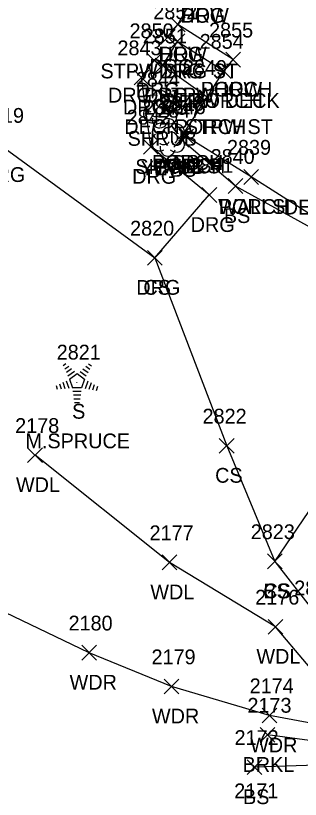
# Model space of a CAD drawing. Extents: x 1499292 to 1501024, y 534584 to 538043.
# Drawn here: x 1499668.2 to 1499706.6, y 537627.9 to 537733.8 of the extents above; entities that cross this region are included whole.
import ezdxf

# ---------------------------------------------------------------- set-up
doc = ezdxf.new("R2010")
doc.units = 0
for name, color, linetype in [('L_A', 7, 'Continuous'), ('L_C', 7, 'Continuous'), ('L_I', 7, 'Continuous'), ('L_TIC', 7, 'Continuous'), ('LAWA', 7, 'Continuous'), ('LAWE', 7, 'Continuous'), ('LBC', 7, 'Continuous'), ('LBF', 7, 'Continuous'), ('LELB', 7, 'Continuous'), ('LSH', 7, 'Continuous'), ('LTC', 7, 'Continuous'), ('LWS', 7, 'Continuous'), ('R_A', 7, 'Continuous'), ('R_I', 7, 'Continuous'), ('R_TIC', 7, 'Continuous'), ('RDG', 7, 'Continuous')]:
    doc.layers.add(name, color=color, linetype=linetype)

msp = doc.modelspace()

# ---------------------------------------------------------------- linework, layer by layer
at = {"layer": 'L_TIC'}
for points in [[(1499689.11, 537731.64), (1499691.11, 537733.64)], [(1499691.11, 537731.64), (1499689.11, 537733.64)], [(1499689.06, 537729.36), (1499691.06, 537731.36)], [(1499691.06, 537729.36), (1499689.06, 537731.36)], [(1499696.59, 537726.89), (1499698.59, 537728.89)], [(1499698.59, 537726.89), (1499696.59, 537728.89)], [(1499696.59, 537726.89), (1499698.59, 537728.89)], [(1499698.59, 537726.89), (1499696.59, 537728.89)], [(1499687.07, 537726.09), (1499689.07, 537728.09)], [(1499689.07, 537726.09), (1499687.07, 537728.09)], [(1499695.32, 537725.36), (1499697.32, 537727.36)], [(1499697.32, 537725.36), (1499695.32, 537727.36)], [(1499695.32, 537725.36), (1499697.32, 537727.36)], [(1499697.32, 537725.36), (1499695.32, 537727.36)], [(1499693.06, 537721.83), (1499695.06, 537723.83)], [(1499695.06, 537721.83), (1499693.06, 537723.83)], [(1499693.06, 537721.83), (1499695.06, 537723.83)], [(1499695.06, 537721.83), (1499693.06, 537723.83)], [(1499689.99, 537716.99), (1499691.99, 537718.99)], [(1499691.99, 537716.99), (1499689.99, 537718.99)], [(1499689.99, 537716.99), (1499691.99, 537718.99)], [(1499691.99, 537716.99), (1499689.99, 537718.99)], [(1499689.59, 537716.05), (1499691.59, 537718.05)], [(1499691.59, 537716.05), (1499689.59, 537718.05)], [(1499690.25, 537716.51), (1499692.25, 537718.51)], [(1499692.25, 537716.51), (1499690.25, 537718.51)], [(1499690.25, 537716.51), (1499692.25, 537718.51)], [(1499692.25, 537716.51), (1499690.25, 537718.51)], [(1499699.02, 537711.03), (1499701.02, 537713.03)], [(1499701.02, 537711.03), (1499699.02, 537713.03)], [(1499699.02, 537711.03), (1499701.02, 537713.03)], [(1499701.02, 537711.03), (1499699.02, 537713.03)], [(1499696.89, 537709.8), (1499698.89, 537711.8)], [(1499698.89, 537709.8), (1499696.89, 537711.8)], [(1499686.02, 537700.1), (1499688.02, 537702.1)], [(1499688.02, 537700.1), (1499686.02, 537702.1)], [(1499695.71, 537674.68), (1499697.71, 537676.68)], [(1499697.71, 537674.68), (1499695.71, 537676.68)], [(1499669.84, 537673.41), (1499671.84, 537675.41)], [(1499671.84, 537673.41), (1499669.84, 537675.41)], [(1499687.98, 537658.91), (1499689.98, 537660.91)], [(1499689.98, 537658.91), (1499687.98, 537660.91)], [(1499702.22, 537659.05), (1499704.22, 537661.05)], [(1499704.22, 537659.05), (1499702.22, 537661.05)], [(1499702.22, 537659.05), (1499704.22, 537661.05)], [(1499704.22, 537659.05), (1499702.22, 537661.05)], [(1499702.31, 537650.2), (1499704.31, 537652.2)], [(1499704.31, 537650.2), (1499702.31, 537652.2)], [(1499677.14, 537646.7), (1499679.14, 537648.7)], [(1499679.14, 537646.7), (1499677.14, 537648.7)], [(1499688.26, 537642.13), (1499690.26, 537644.13)], [(1499690.26, 537642.13), (1499688.26, 537644.13)], [(1499701.5, 537638.21), (1499703.5, 537640.21)], [(1499703.5, 537638.21), (1499701.5, 537640.21)], [(1499701.21, 537635.58), (1499703.21, 537637.58)], [(1499703.21, 537635.58), (1499701.21, 537637.58)], [(1499699.46, 537631.22), (1499701.46, 537633.22)], [(1499701.46, 537631.22), (1499699.46, 537633.22)]]:
    msp.add_lwpolyline(points, dxfattribs=at)
at = {"layer": 'LAWA'}
for points in [[(1499794.25, 537673.22), (1499784.11, 537668.52), (1499774.16, 537666.01), (1499760.16, 537658.55), (1499756.14, 537654.93), (1499740.5, 537649.76), (1499726.86, 537641.25), (1499716.88, 537640.03), (1499711.65, 537641.29), (1499703.31, 537651.2), (1499688.98, 537659.91), (1499670.84, 537674.41)], [(1499794.25, 537673.22), (1499786.26, 537665.9), (1499777.3, 537661.84), (1499770.76, 537658.32), (1499756.42, 537650.43), (1499743.07, 537644.05), (1499716.52, 537636.59), (1499702.5, 537639.21), (1499689.26, 537643.13), (1499678.14, 537647.7), (1499664.49, 537654.21)]]:
    msp.add_lwpolyline(points, dxfattribs=at)
at = {"layer": 'LAWE'}
msp.add_lwpolyline([(1499799.84, 537680.23), (1499787.98, 537665.18), (1499777.71, 537659.05), (1499769.67, 537656.09), (1499756.09, 537648.19), (1499744.55, 537642.26), (1499733.94, 537634.94), (1499716.58, 537634.66), (1499702.21, 537636.58)], dxfattribs=at)
at = {"layer": 'LBC'}
msp.add_lwpolyline([(1499697.59, 537727.89), (1499690.11, 537732.64), (1499693.07, 537737.88), (1499694.33, 537739.7), (1499698.3, 537745.63), (1499698.59, 537746.05), (1499699.21, 537747.22), (1499705.4, 537743.45), (1499710.54, 537740.08), (1499716.25, 537736.71), (1499721.75, 537745), (1499738.99, 537733.64), (1499732.1, 537722.82), (1499729.12, 537718.08), (1499724.69, 537711.28), (1499721.27, 537713.24)], dxfattribs=at)
at = {"layer": 'LBF'}
for points in [[(1499694.06, 537722.83), (1499688.07, 537727.09), (1499690.06, 537730.36), (1499696.32, 537726.36)], [(1499711.51, 537704.76), (1499700.02, 537712.03), (1499691.25, 537717.51), (1499690.99, 537717.99), (1499694.06, 537722.83), (1499696.32, 537726.36), (1499697.59, 537727.89)]]:
    msp.add_lwpolyline(points, dxfattribs=at)
at = {"layer": 'LELB'}
for points in [[(1499931.33, 537841.3), (1499922.8, 537827.37), (1499912.72, 537807.85), (1499905.96, 537796.12), (1499895.82, 537778.01), (1499880.55, 537762.56), (1499870.86, 537749.78), (1499857.65, 537732.09), (1499849.89, 537720.06), (1499839.9, 537710.15), (1499830.87, 537699.25), (1499819.75, 537691.27), (1499813.25, 537682.44), (1499807.24, 537678.73), (1499801.4, 537680.95), (1499789.92, 537664.22), (1499779.13, 537655.09), (1499771.86, 537652.25), (1499758.58, 537645.46), (1499745.45, 537639.29), (1499734.4, 537633.25), (1499715.96, 537632.7), (1499700.46, 537632.22)], [(1499703.22, 537660.05), (1499717.83, 537681.58), (1499716.65, 537701.98), (1499709.84, 537704.22), (1499697.89, 537710.8), (1499690.59, 537717.05), (1499690.99, 537717.99)], [(1499687.02, 537701.1), (1499696.71, 537675.68), (1499703.22, 537660.05), (1499709.09, 537652.45)]]:
    msp.add_lwpolyline(points, dxfattribs=at)
at = {"layer": 'LSH'}
for p, q in [((1499687.7, 537721.24), (1499687.7, 537721.24)), ((1499687.7, 537721.24), (1499687.7, 537721.24)), ((1499688.75, 537717.44), (1499688.75, 537717.44)), ((1499688.75, 537717.44), (1499688.75, 537717.44))]:
    msp.add_line(p, q, dxfattribs=at)
for centre in [(1499687.75, 537722.68), (1499688.79, 537718.87)]:
    msp.add_arc(centre, 1.05, 335.5272, 180.9563, dxfattribs=at)
for centre, major_axis, ratio, start_param, end_param in [((1499686.91, 537721.91), (1.21, -0.51), 0.895232, 1.570796, 4.712389), ((1499688.74, 537721.83), (-1.14, -0.48), 0.949671, 1.570796, 4.712389), ((1499687.49, 537721.7), (-0.208, -0.792), 0.645439, 3.141593, 6.283185), ((1499688.2, 537721.08), (-0.5, 0.667), 0.989748, 3.141593, 6.283185), ((1499686.62, 537720.54), (0.58, -1.04), 0.959034, 3.141593, 6.283185), ((1499688.7, 537720.41), (-1.09, 0.79), 0.841452, 1.570796, 4.712389), ((1499687.7, 537719.74), (0.26, 1.06), 0.942809, 1.570796, 4.712389), ((1499687.24, 537720.49), (-0.625, -0.083), 0.423636, 0, 3.141593), ((1499687.96, 537718.1), (1.21, -0.51), 0.895232, 1.570796, 4.712389), ((1499689.79, 537718.02), (-1.14, -0.48), 0.949671, 1.570796, 4.712389), ((1499688.54, 537717.9), (-0.208, -0.792), 0.645439, 3.141593, 6.283185), ((1499689.25, 537717.27), (-0.5, 0.667), 0.989748, 3.141593, 6.283185), ((1499687.66, 537716.73), (0.58, -1.04), 0.959034, 3.141593, 6.283185), ((1499688.29, 537716.69), (-0.625, -0.083), 0.423636, 0, 3.141593), ((1499689.75, 537716.6), (-1.09, 0.79), 0.841452, 1.570796, 4.712389), ((1499688.75, 537715.94), (0.26, 1.06), 0.942809, 1.570796, 4.712389)]:
    msp.add_ellipse(centre, major_axis=major_axis, ratio=ratio, start_param=start_param, end_param=end_param, dxfattribs=at)
at = {"layer": 'LTC'}
for p, q in [((1499674.65, 537686.54), (1499675.01, 537686.8)), ((1499674.86, 537686.08), (1499675.39, 537686.46)), ((1499675.07, 537685.61), (1499675.78, 537686.12)), ((1499677.31, 537686.09), (1499677.99, 537685.59)), ((1499677.68, 537686.44), (1499678.23, 537686.04)), ((1499678.05, 537686.78), (1499678.47, 537686.48)), ((1499675.28, 537685.15), (1499676.16, 537685.78)), ((1499675.51, 537684.69), (1499676.52, 537685.43)), ((1499676.52, 537685.43), (1499677.51, 537684.7)), ((1499676.94, 537685.74), (1499677.75, 537685.15)), ((1499674.14, 537684.04), (1499674.35, 537683.39)), ((1499674.6, 537684.26), (1499674.87, 537683.42)), ((1499675.05, 537684.47), (1499675.38, 537683.45)), ((1499675.51, 537684.69), (1499675.89, 537683.5)), ((1499677.51, 537684.7), (1499677.12, 537683.5)), ((1499677.95, 537684.43), (1499677.61, 537683.39)), ((1499678.4, 537684.18), (1499678.11, 537683.3)), ((1499678.84, 537683.93), (1499678.6, 537683.2)), ((1499673.68, 537683.82), (1499673.84, 537683.35)), ((1499677.12, 537683.5), (1499675.89, 537683.5)), ((1499677.08, 537683), (1499675.94, 537683)), ((1499679.29, 537683.68), (1499679.1, 537683.11)), ((1499677, 537682.5), (1499676.01, 537682.5)), ((1499676.92, 537682), (1499676.09, 537682)), ((1499676.83, 537681.5), (1499676.16, 537681.5))]:
    msp.add_line(p, q, dxfattribs=at)
at = {"layer": 'LWS'}
msp.add_lwpolyline([(1499730.18, 537700.09), (1499717.54, 537704.27), (1499711.51, 537704.76), (1499700.02, 537712.03), (1499691.25, 537717.51)], dxfattribs=at)
at = {"layer": 'R_TIC'}
for points in [[(1499689.11, 537731.64), (1499691.11, 537733.64)], [(1499691.11, 537731.64), (1499689.11, 537733.64)], [(1499687.77, 537729.96), (1499689.77, 537731.96)], [(1499689.77, 537729.96), (1499687.77, 537731.96)], [(1499689.06, 537729.36), (1499691.06, 537731.36)], [(1499691.06, 537729.36), (1499689.06, 537731.36)], [(1499685.94, 537726.79), (1499687.94, 537728.79)], [(1499687.94, 537726.79), (1499685.94, 537728.79)], [(1499687.07, 537726.09), (1499689.07, 537728.09)], [(1499689.07, 537726.09), (1499687.07, 537728.09)], [(1499684.22, 537724.48), (1499686.22, 537726.48)], [(1499686.22, 537724.48), (1499684.22, 537726.48)], [(1499685.47, 537715.11), (1499687.47, 537717.11)], [(1499687.47, 537715.11), (1499685.47, 537717.11)], [(1499693.36, 537708.59), (1499695.36, 537710.59)], [(1499695.36, 537708.59), (1499693.36, 537710.59)], [(1499686.02, 537700.1), (1499688.02, 537702.1)], [(1499688.02, 537700.1), (1499686.02, 537702.1)]]:
    msp.add_lwpolyline(points, dxfattribs=at)
at = {"layer": 'RDG'}
for points in [[(1499616.25, 537822.18), (1499611.44, 537814.18), (1499628, 537804.72), (1499648.23, 537793.6), (1499657.65, 537787.04), (1499661.23, 537780.56), (1499662.78, 537771.71), (1499664.29, 537756.49), (1499660.39, 537740.63), (1499648.73, 537728.57), (1499635.52, 537714.66), (1499643.06, 537703.46), (1499654.08, 537709.78), (1499666.1, 537716.35), (1499687.02, 537701.1), (1499694.36, 537709.59), (1499686.47, 537716.11), (1499685.22, 537725.48), (1499686.94, 537727.79), (1499688.07, 537727.09)], [(1499690.06, 537730.36), (1499688.77, 537730.96), (1499690.11, 537732.64)]]:
    msp.add_lwpolyline(points, dxfattribs=at)

# ---------------------------------------------------------------- texts
at = {"layer": 'L_A'}
for s, p in [('HOW', (1499690.46, 537732.88)), ('HOW', (1499687.5, 537727.64)), ('STPW DRG ST', (1499679.67, 537725.36)), ('PORCH', (1499693.21, 537722.89)), ('HOW', (1499694.97, 537722.89)), ('DRG STPW', (1499680.69, 537722.09)), ('STPW DECK', (1499687.96, 537721.36)), ('PORCH', (1499691.94, 537721.36)), ('DECK STPW ST', (1499682.88, 537717.83)), ('PORCH', (1499689.69, 537717.83)), ('SHRUB', (1499683.33, 537716.24)), ('PORCH', (1499686.61, 537712.99)), ('BS', (1499689.43, 537712.99)), ('SHRUB', (1499684.38, 537712.44)), ('WALLS', (1499686.79, 537712.51)), ('PORCH', (1499686.87, 537712.51)), ('BS', (1499689.04, 537712.05)), ('WALLS', (1499695.56, 537707.03)), ('PORCH', (1499695.64, 537707.03)), ('DECK2 STPW ST', (1499704.41, 537706.95)), ('BS', (1499696.33, 537705.8)), ('CS', (1499685.46, 537696.1)), ('S', (1499675.84, 537679.34)), ('CS', (1499695.15, 537670.68)), ('WDL', (1499668.26, 537669.41)), ('WDL', (1499686.4, 537654.91)), ('CS', (1499701.66, 537655.05)), ('BS', (1499701.66, 537655.05)), ('WDL', (1499700.72, 537646.2)), ('WDR', (1499675.5, 537642.7)), ('WDR', (1499686.62, 537638.13)), ('WDR', (1499699.87, 537634.21)), ('BRKL', (1499698.85, 537631.58)), ('BS', (1499698.91, 537627.22))]:
    msp.add_text(s, height=2, dxfattribs=at).set_placement(p)
at = {"layer": 'L_C'}
for s, p in [('YEW', (1499685.1, 537712.24)), ('M.SPRUCE', (1499669.54, 537675.34))]:
    msp.add_text(s, height=2, dxfattribs=at).set_placement(p)
at = {"layer": 'L_I'}
for s, p in [('2852', (1499686.8, 537733.36)), ('2855', (1499694.33, 537730.89)), ('2855', (1499694.33, 537730.89)), ('2851', (1499685.38, 537730.09)), ('2854', (1499693.06, 537729.36)), ('2854', (1499693.06, 537729.36)), ('2849', (1499690.8, 537725.83)), ('2849', (1499690.8, 537725.83)), ('2844', (1499684.44, 537724.24)), ('2845', (1499685.49, 537720.44)), ('2847', (1499687.33, 537720.05)), ('2848', (1499687.73, 537720.99)), ('2848', (1499687.73, 537720.99)), ('2846', (1499687.93, 537720.51)), ('2846', (1499687.93, 537720.51)), ('2839', (1499696.75, 537715.03)), ('2839', (1499696.75, 537715.03)), ('2840', (1499694.54, 537713.8)), ('2820', (1499683.67, 537704.1)), ('2821', (1499673.76, 537687.34)), ('2822', (1499693.45, 537678.68)), ('2178', (1499668.15, 537677.41)), ('2177', (1499686.29, 537662.91)), ('2823', (1499699.96, 537663.05)), ('2823', (1499699.96, 537663.05)), ('2824', (1499705.83, 537655.45)), ('2824', (1499705.83, 537655.45)), ('2176', (1499700.56, 537654.2)), ('2180', (1499675.36, 537650.7)), ('2179', (1499686.56, 537646.13)), ('2174', (1499699.81, 537642.21)), ('2173', (1499699.51, 537639.58)), ('2172', (1499697.77, 537635.22)), ('2171', (1499697.72, 537628.01))]:
    msp.add_text(s, height=2, dxfattribs=at).set_placement(p)
at = {"layer": 'LTC'}
msp.add_text('.', height=1.04, rotation=270, dxfattribs=at).set_placement((1499676.4, 537684.44))
at = {"layer": 'R_A'}
for p in [(1499690.56, 537732.88), (1499687.6, 537727.64), (1499686.26, 537725.96), (1499687.55, 537725.36), (1499684.42, 537722.79), (1499685.56, 537722.09), (1499682.71, 537720.48), (1499663.58, 537711.35), (1499683.95, 537711.11), (1499691.85, 537704.59), (1499684.51, 537696.1)]:
    msp.add_text('DRG', height=2, dxfattribs=at).set_placement(p)
at = {"layer": 'R_I'}
for s, p in [('2852', (1499686.8, 537733.36)), ('2850', (1499683.59, 537730.79)), ('2851', (1499685.38, 537730.09)), ('2843', (1499681.96, 537728.48)), ('2819', (1499663.4, 537719.35)), ('2842', (1499683.21, 537719.11)), ('2841', (1499691.66, 537712.59)), ('2820', (1499683.67, 537704.1))]:
    msp.add_text(s, height=2, dxfattribs=at).set_placement(p)

doc.saveas('drawing.dxf')
